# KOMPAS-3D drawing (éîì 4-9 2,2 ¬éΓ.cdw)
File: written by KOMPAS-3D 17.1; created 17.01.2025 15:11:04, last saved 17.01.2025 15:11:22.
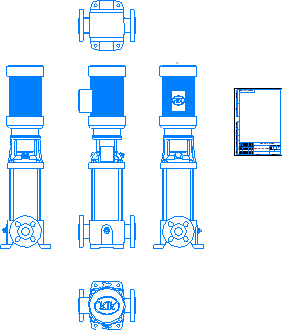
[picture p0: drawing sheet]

Sheet 1: A4, portrait

Title block, sheet 1: name: ВМН 4-9 2,2 кВт; designation: ВМН 4-9 2,2 кВт; sheets: 1; sheet format: A4; stored path: \\adlc.lan\data\АДЛ_ПКД\3D-модели\ADL production\Насосы ГРАНПАМП\Насосы ВМН\ВМН4\KOMPAS 2D\ВМН 4-9 2,2 кВт.cdw

Views: Вид 1, Спереди, Проекционный вид 2, Проекционный вид 3, Проекционный вид 4, Проекционный вид 5
Referenced files in \\adlc.lan\data\АДЛ_ПКД\3D-модели\ADL production\Насосы ГРАНПАМП\Насосы ВМН\ВМН4\KOMPAS 3D\: ВМН 4-9 2,2 кВт.m3d
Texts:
  Andrey
  АДЛ
Dimensions and other numbers on the sheet: 1:1; 1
